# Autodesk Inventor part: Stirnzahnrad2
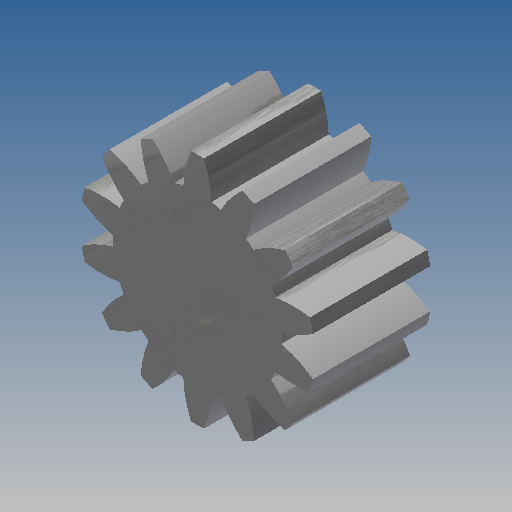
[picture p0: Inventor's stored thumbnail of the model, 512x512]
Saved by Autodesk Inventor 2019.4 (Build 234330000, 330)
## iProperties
Created: 2021-12
Part Number: Stirnzahnrad2
Material: Steel
Document SubType Name: Modeling
Categories: <?xml version="1.0" encoding="UTF-16"?> <MemberInstance><Categories><FamilyTemplate><FamilyTemplateParameter ValueType="xs:double" Id="1" ObjectReferenceKey="da
Mass: 1.20092 g
Surface Area: 2.53379 cm^2
Volume: 0.152983 cm^3
Density: 7.85 g/cm^3
Appearance: Steel
CustomPartVersion: 1
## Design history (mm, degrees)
sketch "Sketch1"
  geometry: C1 r 4 at (0, 0)
  constraints: 1 centre point
  dimensions: "d0" = 8 diameter of C1 (= da_da)
extrude "Extrusion1" new body sketch "Sketch1" distance "d1" = 4 (= da_b); taper "d2" = 0 deg
workplane "Work Plane2"
sketch "Sketch2"
  geometry: C1 r 4 at (0, 0) reference; C2 r 3.5 at (0, 0)
  constraints: 1 centre point, 1 coincident
  dimensions: "d3" = 7 diameter of C2 (= da_dw)
feature "Flankendurchmesser" sketch "Sketch2" dims "d4" = 10, "d5" = 0
workplane "Work Plane8"
workplane "Work Plane9"
feature "Stirnzahnrad" dims "da_b" = 4, "da_d" = 7, "da_aw" = 35.5, "da_da" = 8, "da_df" = 5.75, "da_dw" = 7, angle "da_beta" = 0 deg, "da_lefttooth" = 0, "da_righttooth" = 0
body "Solid1"
body "Srf1"
other parameters: "d16" = 35.5 (= da_aw), "d17" = 0, "d34" = 2.24399 (computed from da_z), "d39" = 0, "d41" = 0, "d43" = 35.5 (= da_aw), "d46" = 35.5 (= da_aw), "d47" = 0, "d48" = 0
